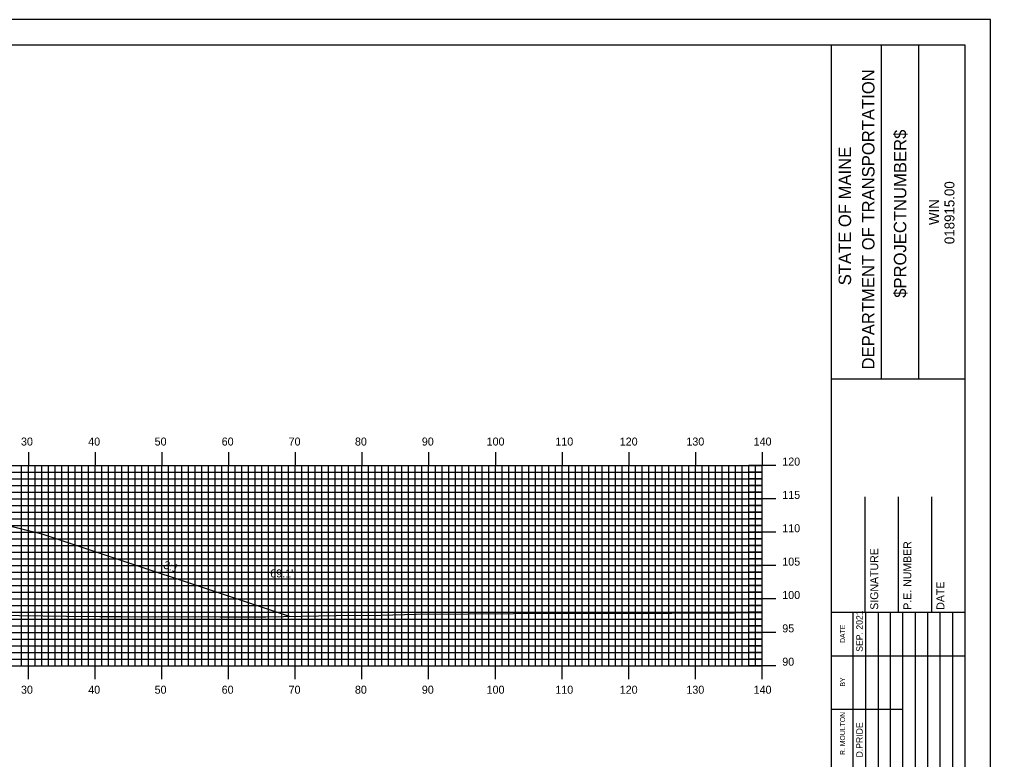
# Model space of a CAD drawing. Extents: x 1787369 to 1787713, y 442591 to 442811.
# Drawn here: x 1787563.8 to 1787709.3, y 442699.6 to 442810.5 of the extents above; entities that cross this region are included whole.
import ezdxf

# ---------------------------------------------------------------- set-up
doc = ezdxf.new("R2010")
doc.units = 0
for name, color, linetype in [('ANNOTATION', 7, 'Continuous'), ('BORDER', 7, 'Continuous'), ('D_Roadway_Centerline', 7, 'Continuous'), ('D_Roadway_SlopeLines', 7, 'Continuous'), ('D_Text_Standard', 7, 'Continuous'), ('H_V ANNOTATION', 7, 'Continuous'), ('MAJOR', 7, 'Continuous'), ('MINOR', 7, 'Continuous'), ('PLOT BOUNDARY', 7, 'Continuous'), ('S_Roadway_Centerline', 7, 'Continuous')]:
    doc.layers.add(name, color=color, linetype=linetype)

msp = doc.modelspace()

# ---------------------------------------------------------------- linework, layer by layer
at = {"layer": 'BORDER'}
for p, q in [((1787685.5, 442596.67), (1787685.5, 442806.67)), ((1787692.96, 442756.66), (1787692.96, 442806.66)), ((1787698.55, 442756.66), (1787698.55, 442806.66)), ((1787685.51, 442756.65), (1787705.5, 442756.65)), ((1787690.5, 442721.67), (1787690.5, 442738.97)), ((1787695.5, 442721.67), (1787695.5, 442738.97)), ((1787700.5, 442721.67), (1787700.5, 442738.97)), ((1787685.5, 442721.67), (1787705.5, 442721.67))]:
    msp.add_line(p, q, dxfattribs=at)
msp.add_lwpolyline([(1787385.5, 442596.67), (1787705.5, 442596.67), (1787705.5, 442806.67), (1787385.5, 442806.67)], close=True, dxfattribs=at)
for points in [[(1787688.73, 442715.17), (1787688.73, 442721.67)], [(1787690.6, 442686.68), (1787690.6, 442721.67)], [(1787692.46, 442721.67), (1787692.46, 442686.68)], [(1787694.33, 442686.68), (1787694.33, 442721.67)], [(1787696.19, 442686.68), (1787696.19, 442721.67)], [(1787698.05, 442686.68), (1787698.05, 442721.67)], [(1787699.92, 442686.68), (1787699.92, 442721.67)], [(1787701.78, 442686.68), (1787701.78, 442721.67)], [(1787703.64, 442686.68), (1787703.64, 442721.67)], [(1787688.74, 442686.68), (1787688.74, 442720.26)], [(1787685.5, 442715.17), (1787705.5, 442715.17)], [(1787685.5, 442707.17), (1787688.74, 442707.17)], [(1787688.73, 442707.17), (1787696.19, 442707.17)]]:
    msp.add_lwpolyline(points, dxfattribs=at)
at = {"layer": 'D_Roadway_Centerline'}
msp.add_lwpolyline([(1787469.92, 442721.85), (1787503.1, 442732.91), (1787506.74, 442733.82), (1787515.1, 442735.91), (1787523.1, 442736.23), (1787535.1, 442736.49), (1787547.1, 442736.76), (1787555.1, 442736.44), (1787563.47, 442734.35), (1787567.1, 442733.44), (1787604.19, 442721.08)], dxfattribs=at)
at = {"layer": 'D_Roadway_SlopeLines'}
msp.add_lwpolyline([(1787555.1, 442736.44), (1787567.1, 442733.44), (1787604.19, 442721.08)], dxfattribs=at)
at = {"layer": 'MAJOR'}
for p, q in [((1787565.1, 442745.67), (1787565.1, 442743.67)), ((1787575.1, 442745.67), (1787575.1, 442743.67)), ((1787585.1, 442745.67), (1787585.1, 442743.67)), ((1787595.1, 442745.67), (1787595.1, 442743.67)), ((1787605.1, 442745.67), (1787605.1, 442743.67)), ((1787615.1, 442745.67), (1787615.1, 442743.67)), ((1787625.1, 442745.67), (1787625.1, 442743.67)), ((1787635.1, 442745.67), (1787635.1, 442743.67)), ((1787645.1, 442745.67), (1787645.1, 442743.67)), ((1787655.1, 442745.67), (1787655.1, 442743.67)), ((1787665.1, 442745.67), (1787665.1, 442743.67)), ((1787675.1, 442745.67), (1787675.1, 442743.67)), ((1787395.1, 442743.67), (1787675.1, 442743.67)), ((1787395.1, 442743.67), (1787675.1, 442743.67)), ((1787565.1, 442713.67), (1787565.1, 442743.67)), ((1787575.1, 442713.67), (1787575.1, 442743.67)), ((1787585.1, 442713.67), (1787585.1, 442743.67)), ((1787595.1, 442713.67), (1787595.1, 442743.67)), ((1787605.1, 442713.67), (1787605.1, 442743.67)), ((1787615.1, 442713.67), (1787615.1, 442743.67)), ((1787625.1, 442713.67), (1787625.1, 442743.67)), ((1787635.1, 442713.67), (1787635.1, 442743.67)), ((1787645.1, 442713.67), (1787645.1, 442743.67)), ((1787655.1, 442713.67), (1787655.1, 442743.67)), ((1787665.1, 442713.67), (1787665.1, 442743.67)), ((1787677.11, 442743.67), (1787673.1, 442743.67)), ((1787675.1, 442713.67), (1787675.1, 442743.67)), ((1787675.1, 442713.67), (1787675.1, 442743.67)), ((1787395.1, 442738.67), (1787675.1, 442738.67)), ((1787677.11, 442738.67), (1787673.1, 442738.67)), ((1787395.1, 442733.67), (1787675.1, 442733.67)), ((1787677.11, 442733.67), (1787673.1, 442733.67)), ((1787395.1, 442728.67), (1787675.1, 442728.67)), ((1787677.11, 442728.67), (1787673.1, 442728.67)), ((1787395.1, 442723.67), (1787675.1, 442723.67)), ((1787677.11, 442723.67), (1787673.1, 442723.67)), ((1787395.1, 442718.67), (1787675.1, 442718.67)), ((1787677.11, 442718.67), (1787673.1, 442718.67)), ((1787395.1, 442713.67), (1787675.1, 442713.67)), ((1787395.1, 442713.67), (1787675.1, 442713.67)), ((1787565.1, 442711.66), (1787565.1, 442713.67)), ((1787575.1, 442711.66), (1787575.1, 442713.67)), ((1787585.1, 442711.66), (1787585.1, 442713.67)), ((1787595.1, 442711.66), (1787595.1, 442713.67)), ((1787605.1, 442711.66), (1787605.1, 442713.67)), ((1787615.1, 442711.66), (1787615.1, 442713.67)), ((1787625.1, 442711.66), (1787625.1, 442713.67)), ((1787635.1, 442711.66), (1787635.1, 442713.67)), ((1787645.1, 442711.66), (1787645.1, 442713.67)), ((1787655.1, 442711.66), (1787655.1, 442713.67)), ((1787665.1, 442711.66), (1787665.1, 442713.67)), ((1787677.11, 442713.67), (1787673.1, 442713.67)), ((1787675.1, 442711.66), (1787675.1, 442713.67))]:
    msp.add_line(p, q, dxfattribs=at)
at = {"layer": 'MINOR'}
for p, q in [((1787564.1, 442713.67), (1787564.1, 442743.67)), ((1787566.1, 442713.67), (1787566.1, 442743.67)), ((1787567.1, 442713.67), (1787567.1, 442743.67)), ((1787568.1, 442713.67), (1787568.1, 442743.67)), ((1787569.1, 442713.67), (1787569.1, 442743.67)), ((1787570.1, 442713.67), (1787570.1, 442743.67)), ((1787571.1, 442713.67), (1787571.1, 442743.67)), ((1787572.1, 442713.67), (1787572.1, 442743.67)), ((1787573.1, 442713.67), (1787573.1, 442743.67)), ((1787574.1, 442713.67), (1787574.1, 442743.67)), ((1787576.1, 442713.67), (1787576.1, 442743.67)), ((1787577.1, 442713.67), (1787577.1, 442743.67)), ((1787578.1, 442713.67), (1787578.1, 442743.67)), ((1787579.1, 442713.67), (1787579.1, 442743.67)), ((1787580.1, 442713.67), (1787580.1, 442743.67)), ((1787581.1, 442713.67), (1787581.1, 442743.67)), ((1787582.1, 442713.67), (1787582.1, 442743.67)), ((1787583.1, 442713.67), (1787583.1, 442743.67)), ((1787584.1, 442713.67), (1787584.1, 442743.67)), ((1787586.1, 442713.67), (1787586.1, 442743.67)), ((1787587.1, 442713.67), (1787587.1, 442743.67)), ((1787588.1, 442713.67), (1787588.1, 442743.67)), ((1787589.1, 442713.67), (1787589.1, 442743.67)), ((1787590.1, 442713.67), (1787590.1, 442743.67)), ((1787591.1, 442713.67), (1787591.1, 442743.67)), ((1787592.1, 442713.67), (1787592.1, 442743.67)), ((1787593.1, 442713.67), (1787593.1, 442743.67)), ((1787594.1, 442713.67), (1787594.1, 442743.67)), ((1787596.1, 442713.67), (1787596.1, 442743.67)), ((1787597.1, 442713.67), (1787597.1, 442743.67)), ((1787598.1, 442713.67), (1787598.1, 442743.67)), ((1787599.1, 442713.67), (1787599.1, 442743.67)), ((1787600.1, 442713.67), (1787600.1, 442743.67)), ((1787601.1, 442713.67), (1787601.1, 442743.67)), ((1787602.1, 442713.67), (1787602.1, 442743.67)), ((1787603.1, 442713.67), (1787603.1, 442743.67)), ((1787604.1, 442713.67), (1787604.1, 442743.67)), ((1787606.1, 442713.67), (1787606.1, 442743.67)), ((1787607.1, 442713.67), (1787607.1, 442743.67)), ((1787608.1, 442713.67), (1787608.1, 442743.67)), ((1787609.1, 442713.67), (1787609.1, 442743.67)), ((1787610.1, 442713.67), (1787610.1, 442743.67)), ((1787611.1, 442713.67), (1787611.1, 442743.67)), ((1787612.1, 442713.67), (1787612.1, 442743.67)), ((1787613.1, 442713.67), (1787613.1, 442743.67)), ((1787614.1, 442713.67), (1787614.1, 442743.67)), ((1787616.1, 442713.67), (1787616.1, 442743.67)), ((1787617.1, 442713.67), (1787617.1, 442743.67)), ((1787618.1, 442713.67), (1787618.1, 442743.67)), ((1787619.1, 442713.67), (1787619.1, 442743.67)), ((1787620.1, 442713.67), (1787620.1, 442743.67)), ((1787621.1, 442713.67), (1787621.1, 442743.67)), ((1787622.1, 442713.67), (1787622.1, 442743.67)), ((1787623.1, 442713.67), (1787623.1, 442743.67)), ((1787624.1, 442713.67), (1787624.1, 442743.67)), ((1787626.1, 442713.67), (1787626.1, 442743.67)), ((1787627.1, 442713.67), (1787627.1, 442743.67)), ((1787628.1, 442713.67), (1787628.1, 442743.67)), ((1787629.1, 442713.67), (1787629.1, 442743.67)), ((1787630.1, 442713.67), (1787630.1, 442743.67)), ((1787631.1, 442713.67), (1787631.1, 442743.67)), ((1787632.1, 442713.67), (1787632.1, 442743.67)), ((1787633.1, 442713.67), (1787633.1, 442743.67)), ((1787634.1, 442713.67), (1787634.1, 442743.67)), ((1787636.1, 442713.67), (1787636.1, 442743.67)), ((1787637.1, 442713.67), (1787637.1, 442743.67)), ((1787638.1, 442713.67), (1787638.1, 442743.67)), ((1787639.1, 442713.67), (1787639.1, 442743.67)), ((1787640.1, 442713.67), (1787640.1, 442743.67)), ((1787641.1, 442713.67), (1787641.1, 442743.67)), ((1787642.1, 442713.67), (1787642.1, 442743.67)), ((1787643.1, 442713.67), (1787643.1, 442743.67)), ((1787644.1, 442713.67), (1787644.1, 442743.67)), ((1787646.1, 442713.67), (1787646.1, 442743.67)), ((1787647.1, 442713.67), (1787647.1, 442743.67)), ((1787648.1, 442713.67), (1787648.1, 442743.67)), ((1787649.1, 442713.67), (1787649.1, 442743.67)), ((1787650.1, 442713.67), (1787650.1, 442743.67)), ((1787651.1, 442713.67), (1787651.1, 442743.67)), ((1787652.1, 442713.67), (1787652.1, 442743.67)), ((1787653.1, 442713.67), (1787653.1, 442743.67)), ((1787654.1, 442713.67), (1787654.1, 442743.67)), ((1787656.1, 442713.67), (1787656.1, 442743.67)), ((1787657.1, 442713.67), (1787657.1, 442743.67)), ((1787658.1, 442713.67), (1787658.1, 442743.67)), ((1787659.1, 442713.67), (1787659.1, 442743.67)), ((1787660.1, 442713.67), (1787660.1, 442743.67)), ((1787661.1, 442713.67), (1787661.1, 442743.67)), ((1787662.1, 442713.67), (1787662.1, 442743.67)), ((1787663.1, 442713.67), (1787663.1, 442743.67)), ((1787664.1, 442713.67), (1787664.1, 442743.67)), ((1787666.1, 442713.67), (1787666.1, 442743.67)), ((1787667.1, 442713.67), (1787667.1, 442743.67)), ((1787668.1, 442713.67), (1787668.1, 442743.67)), ((1787669.1, 442713.67), (1787669.1, 442743.67)), ((1787670.1, 442713.67), (1787670.1, 442743.67)), ((1787671.1, 442713.67), (1787671.1, 442743.67)), ((1787672.1, 442713.67), (1787672.1, 442743.67)), ((1787673.1, 442713.67), (1787673.1, 442743.67)), ((1787674.1, 442713.67), (1787674.1, 442743.67)), ((1787395.1, 442742.67), (1787675.1, 442742.67)), ((1787395.1, 442741.67), (1787675.1, 442741.67)), ((1787675.1, 442742.67), (1787673.1, 442742.67)), ((1787675.1, 442741.67), (1787673.1, 442741.67)), ((1787395.1, 442740.67), (1787675.1, 442740.67)), ((1787675.1, 442740.67), (1787673.1, 442740.67)), ((1787395.1, 442739.67), (1787675.1, 442739.67)), ((1787675.1, 442739.67), (1787673.1, 442739.67)), ((1787395.1, 442737.67), (1787675.1, 442737.67)), ((1787675.1, 442737.67), (1787673.1, 442737.67)), ((1787395.1, 442736.67), (1787675.1, 442736.67)), ((1787395.1, 442735.67), (1787675.1, 442735.67)), ((1787675.1, 442736.67), (1787673.1, 442736.67)), ((1787675.1, 442735.67), (1787673.1, 442735.67)), ((1787395.1, 442734.67), (1787675.1, 442734.67)), ((1787675.1, 442734.67), (1787673.1, 442734.67)), ((1787395.1, 442732.67), (1787675.1, 442732.67)), ((1787675.1, 442732.67), (1787673.1, 442732.67)), ((1787395.1, 442731.67), (1787675.1, 442731.67)), ((1787675.1, 442731.67), (1787673.1, 442731.67)), ((1787395.1, 442730.67), (1787675.1, 442730.67)), ((1787675.1, 442730.67), (1787673.1, 442730.67)), ((1787395.1, 442729.67), (1787675.1, 442729.67)), ((1787675.1, 442729.67), (1787673.1, 442729.67)), ((1787395.1, 442727.67), (1787675.1, 442727.67)), ((1787675.1, 442727.67), (1787673.1, 442727.67)), ((1787395.1, 442726.67), (1787675.1, 442726.67)), ((1787395.1, 442725.67), (1787675.1, 442725.67)), ((1787675.1, 442726.67), (1787673.1, 442726.67)), ((1787675.1, 442725.67), (1787673.1, 442725.67)), ((1787395.1, 442724.67), (1787675.1, 442724.67)), ((1787675.1, 442724.67), (1787673.1, 442724.67)), ((1787395.1, 442722.67), (1787675.1, 442722.67)), ((1787675.1, 442722.67), (1787673.1, 442722.67)), ((1787395.1, 442721.67), (1787675.1, 442721.67)), ((1787675.1, 442721.67), (1787673.1, 442721.67)), ((1787395.1, 442720.67), (1787675.1, 442720.67)), ((1787395.1, 442719.67), (1787675.1, 442719.67)), ((1787675.1, 442720.67), (1787673.1, 442720.67)), ((1787675.1, 442719.67), (1787673.1, 442719.67)), ((1787395.1, 442717.67), (1787675.1, 442717.67)), ((1787395.1, 442716.67), (1787675.1, 442716.67)), ((1787675.1, 442717.67), (1787673.1, 442717.67)), ((1787675.1, 442716.67), (1787673.1, 442716.67)), ((1787395.1, 442715.67), (1787675.1, 442715.67)), ((1787675.1, 442715.67), (1787673.1, 442715.67)), ((1787395.1, 442714.67), (1787675.1, 442714.67)), ((1787675.1, 442714.67), (1787673.1, 442714.67))]:
    msp.add_line(p, q, dxfattribs=at)
at = {"layer": 'PLOT BOUNDARY'}
msp.add_lwpolyline([(1787369.32, 442590.55), (1787709.32, 442590.55), (1787709.32, 442810.55), (1787369.32, 442810.55)], close=True, dxfattribs=at)
at = {"layer": 'S_Roadway_Centerline'}
msp.add_lwpolyline([(1787559.31, 442721.23), (1787563.78, 442721.19), (1787570.83, 442721.1), (1787575.84, 442721.05), (1787579.04, 442721.05), (1787593.87, 442721), (1787598.31, 442720.98), (1787600.68, 442721.01), (1787611.25, 442721.21), (1787618, 442721.25), (1787623.22, 442721.38), (1787631.05, 442721.43), (1787637.83, 442721.51), (1787647.14, 442721.55), (1787657.31, 442721.5), (1787661.57, 442721.52), (1787670.88, 442721.59), (1787675.1, 442721.64)], dxfattribs=at)

# ---------------------------------------------------------------- texts
at = {"layer": 'ANNOTATION'}
msp.add_text('3:1', height=1.2, rotation=341.5652, dxfattribs=at).set_placement((1787585.25, 442728.3))
at = {"layer": 'BORDER'}
for s, height, p in [('DEPARTMENT OF TRANSPORTATION', 1.8635, (1787691.92, 442758.08)), ('$PROJECTNUMBER$', 1.8635, (1787696.69, 442768.82)), ('STATE OF MAINE', 1.8635, (1787688.41, 442770.69)), ('018915.00', 1.491, (1787703.9, 442776.86)), ('WIN', 1.491, (1787701.58, 442779.73)), ('P.E. NUMBER', 1.1811, (1787697.43, 442722.06)), ('SIGNATURE', 1.181, (1787692.47, 442722.06)), ('DATE', 1.181, (1787702.39, 442722.06)), ('SEP. 2021', 0.969, (1787690.15, 442715.76)), ('DATE', 0.743, (1787687.51, 442717.08)), ('BY', 0.743, (1787687.51, 442710.54)), ('R. MOULTON', 0.745, (1787687.51, 442700.28)), ('D.PRIDE', 0.969, (1787690.15, 442699.92))]:
    msp.add_text(s, height=height, rotation=90, dxfattribs=at).set_placement(p)
at = {"layer": 'D_Text_Standard'}
msp.add_text("69.1'", height=1.2, dxfattribs=at).set_placement((1787601.36, 442726.9))
at = {"layer": 'H_V ANNOTATION'}
for s, p in [('30', (1787564, 442746.67)), ('40', (1787574.08, 442746.67)), ('50', (1787584.03, 442746.67)), ('60', (1787594.08, 442746.67)), ('70', (1787604.11, 442746.67)), ('80', (1787614.05, 442746.67)), ('90', (1787624.08, 442746.67)), ('100', (1787633.79, 442746.67)), ('110', (1787644.09, 442746.67)), ('120', (1787653.74, 442746.67)), ('130', (1787663.73, 442746.67)), ('140', (1787673.81, 442746.67)), ('120', (1787678.1, 442743.67)), ('115', (1787678.1, 442738.67)), ('110', (1787678.1, 442733.67)), ('105', (1787678.1, 442728.67)), ('100', (1787678.1, 442723.67)), ('95', (1787678.1, 442718.67)), ('90', (1787678.1, 442713.67)), ('30', (1787564, 442709.47)), ('40', (1787574.08, 442709.47)), ('50', (1787584.03, 442709.47)), ('60', (1787594.08, 442709.47)), ('70', (1787604.11, 442709.47)), ('80', (1787614.05, 442709.47)), ('90', (1787624.08, 442709.47)), ('100', (1787633.79, 442709.47)), ('110', (1787644.09, 442709.47)), ('120', (1787653.74, 442709.47)), ('130', (1787663.73, 442709.47)), ('140', (1787673.81, 442709.47))]:
    msp.add_text(s, height=1.2, dxfattribs=at).set_placement(p)

doc.saveas('drawing.dxf')
